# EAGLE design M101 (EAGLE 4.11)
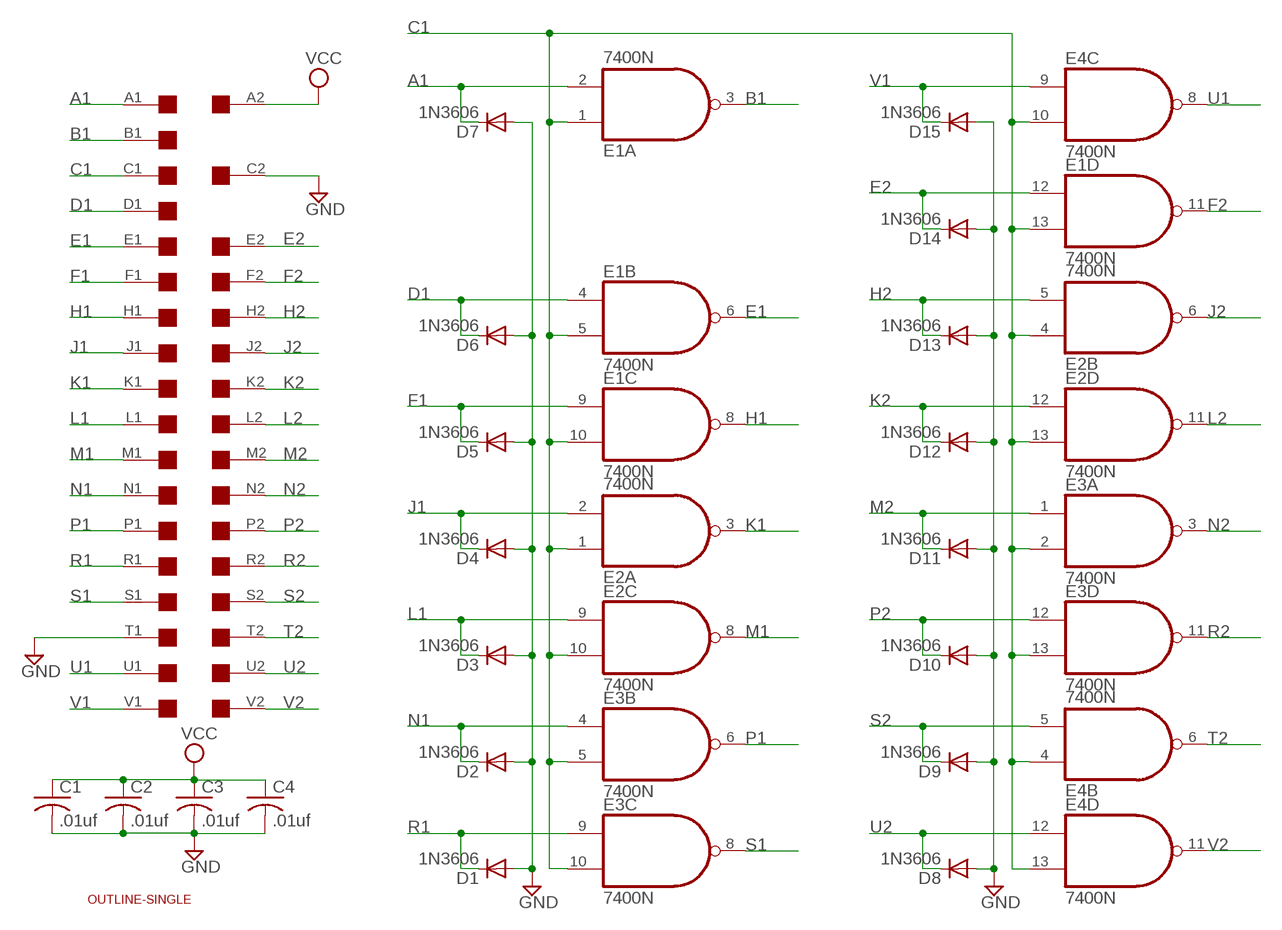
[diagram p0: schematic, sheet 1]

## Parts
C1  .01uf  C-US050-025X075  [C050-025X075]
C2  .01uf  C-US050-025X075  [C050-025X075]
C3  .01uf  C-US050-025X075  [C050-025X075]
C4  .01uf  C-US050-025X075  [C050-025X075]
D1  1N3606  1N4148  [DO35-10]
D2  1N3606  1N4148  [DO35-10]
D3  1N3606  1N4148  [DO35-10]
D4  1N3606  1N4148  [DO35-10]
D5  1N3606  1N4148  [DO35-10]
D6  1N3606  1N4148  [DO35-10]
D7  1N3606  1N4148  [DO35-10]
D8  1N3606  1N4148  [DO35-10]
D9  1N3606  1N4148  [DO35-10]
D10  1N3606  1N4148  [DO35-10]
D11  1N3606  1N4148  [DO35-10]
D12  1N3606  1N4148  [DO35-10]
D13  1N3606  1N4148  [DO35-10]
D14  1N3606  1N4148  [DO35-10]
D15  1N3606  1N4148  [DO35-10]
E1  7400N  [DIL14]
E2  7400N  [DIL14]
E3  7400N  [DIL14]
E4  7400N  [DIL14]
U$1  SINGLE  [EDGE-CON2]
U$4  OUTLINE-SINGLE  [SINGLE]

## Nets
A1: D7.C E1.2(A:I1) U$1.A1
B1: E1.3(A:O) U$1.B1
C1: E1.1(A:I0) E1.5(B:I1) E1.10(C:I1) E1.13(D:I1) E2.1(A:I0) E2.4(B:I0) E2.10(C:I1) E2.13(D:I1) E3.2(A:I1) E3.5(B:I1) E3.10(C:I1) E3.13(D:I1) E4.4(B:I0) E4.10(C:I1) E4.13(D:I1) U$1.C1
D1: D6.C E1.4(B:I0) U$1.D1
E1: E1.6(B:O) U$1.E1
E2: D14.C E1.12(D:I0) U$1.E2
F1: D5.C E1.9(C:I0) U$1.F1
F2: E1.11(D:O) U$1.F2
GND: C1.2 C2.2 C3.2 C4.2 D1.A D2.A D3.A D4.A D5.A D6.A D7.A D8.A D9.A D10.A D11.A D12.A D13.A D14.A D15.A U$1.C2 U$1.T1
H1: E1.8(C:O) U$1.H1
H2: D13.C E2.5(B:I1) U$1.H2
J1: D4.C E2.2(A:I1) U$1.J1
J2: E2.6(B:O) U$1.J2
K1: E2.3(A:O) U$1.K1
K2: D12.C E2.12(D:I0) U$1.K2
L1: D3.C E2.9(C:I0) U$1.L1
L2: E2.11(D:O) U$1.L2
M1: E2.8(C:O) U$1.M1
M2: D11.C E3.1(A:I0) U$1.M2
N1: D2.C E3.4(B:I0) U$1.N1
N2: E3.3(A:O) U$1.N2
P1: E3.6(B:O) U$1.P1
P2: D10.C E3.12(D:I0) U$1.P2
R1: D1.C E3.9(C:I0) U$1.R1
R2: E3.11(D:O) U$1.R2
S1: E3.8(C:O) U$1.S1
S2: D9.C E4.5(B:I1) U$1.S2
T2: E4.6(B:O) U$1.T2
U1: E4.8(C:O) U$1.U1
U2: D8.C E4.12(D:I0) U$1.U2
V1: D15.C E4.9(C:I0) U$1.V1
V2: E4.11(D:O) U$1.V2
VCC: C1.1 C2.1 C3.1 C4.1 U$1.A2
Unconnected: E4.1(A:I0) E4.2(A:I1) E4.3(A:O) U$1.B2 U$1.D2

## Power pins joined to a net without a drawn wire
GND: E1.7(P:GND) E2.7(P:GND) E3.7(P:GND) E4.7(P:GND)
VCC: E1.14(P:VCC) E2.14(P:VCC) E3.14(P:VCC) E4.14(P:VCC)

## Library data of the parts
C1-C4 = rcl:C-US: CAPACITOR, American symbol
D1-D15 = diode:1N4148: DIODE
E1-E4 = 74xx-us:74*00: Quad 2-input NAND gate
U$1 = dec-con:SINGLE: Single-Height DEC board
U$4 = dec-con:OUTLINE-*: Board outlines for DEC boards.

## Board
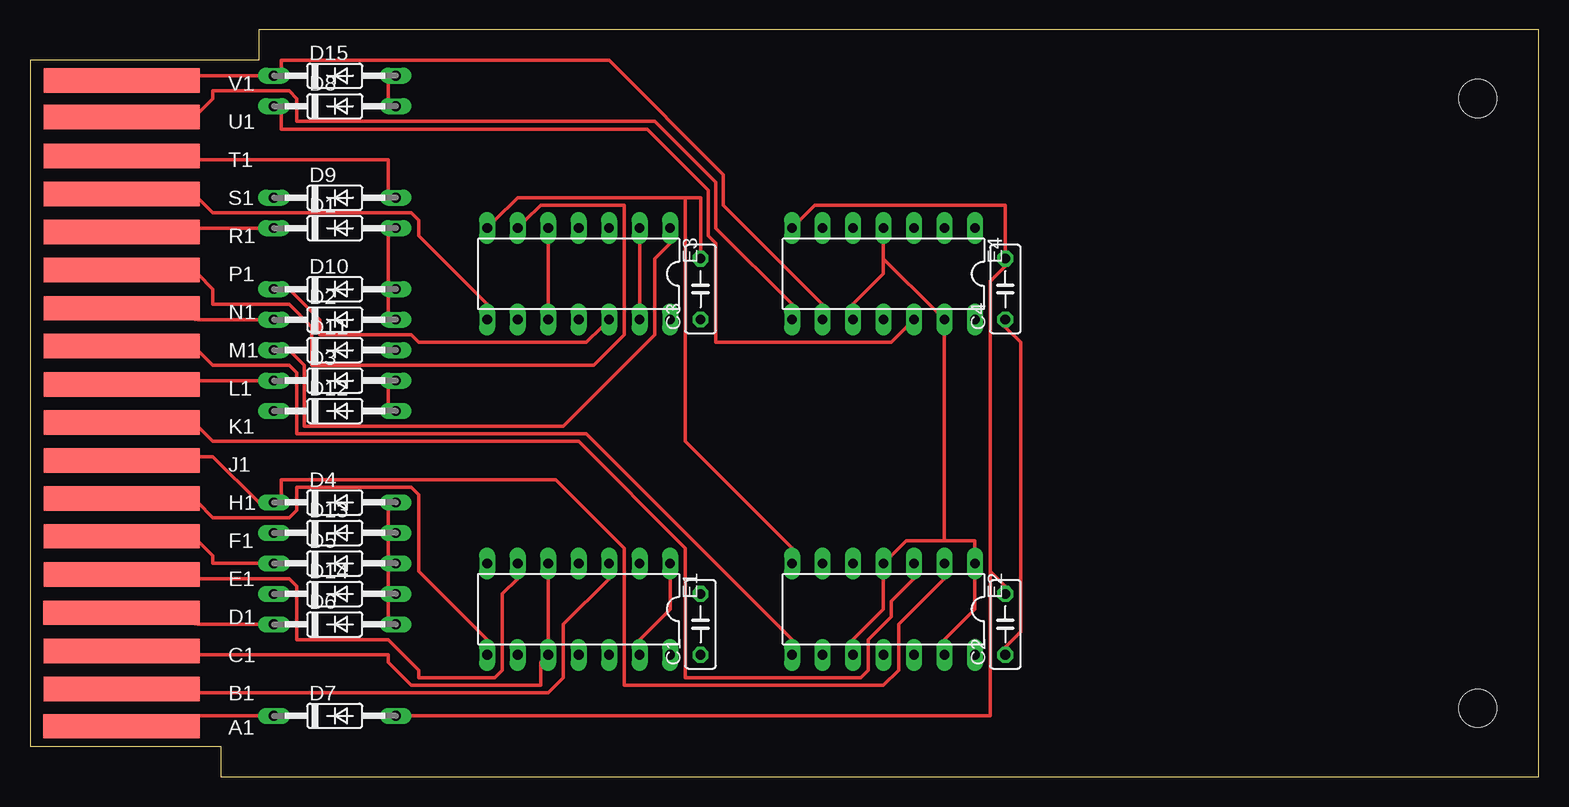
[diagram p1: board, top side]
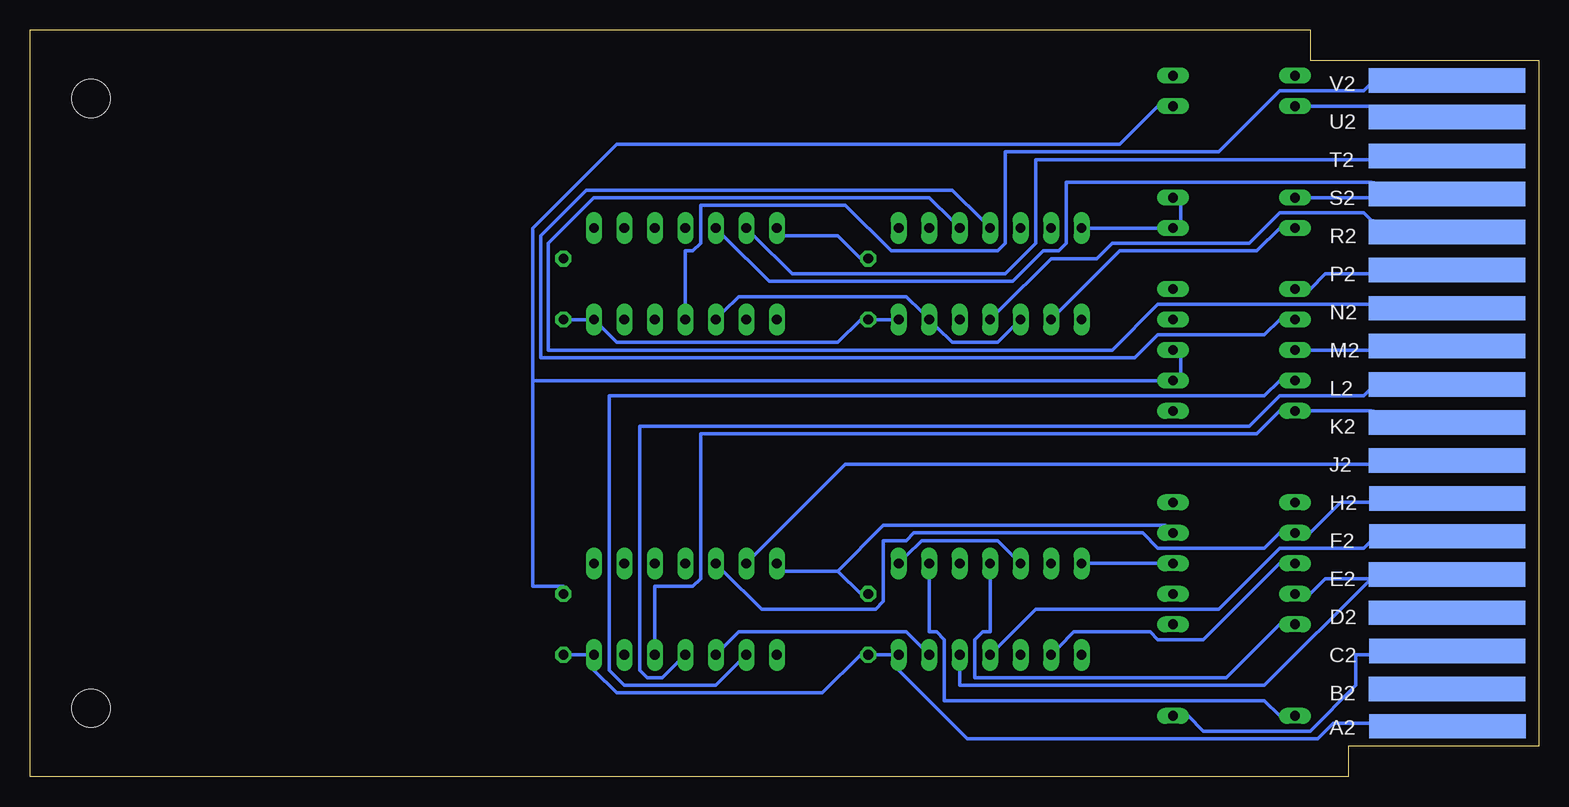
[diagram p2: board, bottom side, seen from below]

Size 125.73 x 62.23 mm. Coordinates in mm from the lower left corner, seen from the top.
Copper layers (1*16): Top 0.035mm / dielectric 1.5mm / Bottom 0.035mm
Design rules "10mils": minimum track width 12mil, minimum drill 28mil, track to track 10mil, track to pad 10mil, pad to pad 10mil, via to via 10mil, smd to smd 10mil, copper to edge 40mil, drill to drill 10mil, minimum pad ring 10mil, minimum via ring 8mil, stop-mask expansion 0mil, vias tented up to drill 0mil, thermal gap 10mil

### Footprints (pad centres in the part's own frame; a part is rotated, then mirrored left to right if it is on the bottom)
C050-025X075 = drill 0.813 octagon: 1 -2.54,0; 2 2.54,0
DO35-10 = drill 0.813 long: A 5.08,0; C -5.08,0
DIL14 = drill 0.813 long: 1 -7.62,-3.81; 2 -5.08,-3.81; 3 -2.54,-3.81; 4 0,-3.81; 5 2.54,-3.81; 6 5.08,-3.81; 7 7.62,-3.81; 8 7.62,3.81; 9 5.08,3.81; 10 2.54,3.81; 11 0,3.81; 12 -2.54,3.81; 13 -5.08,3.81; 14 -7.62,3.81
EDGE-CON2 = smd 13.017 x 2.032: A1 7.633,4.207; B1 7.639,7.327; C1 7.636,10.489; D1 7.633,13.665; E1 7.642,16.84; F1 7.642,20.041; H1 7.642,23.19; J1 7.642,26.34; K1 7.642,29.515; L1 7.642,32.69; M1 7.642,35.89; N1 7.642,39.04; P1 7.642,42.24; R1 7.642,45.39; S1 7.642,48.565; T1 7.642,51.74; U1 7.642,54.966; V1 7.642,58.026 | smd 13.017 x 2.032 bottom: A2 7.614,4.207; B2 7.642,7.328; C2 7.617,10.49; D2 7.642,13.665; E2 7.642,16.84; F2 7.617,20.041; H2 7.617,23.19; J2 7.642,26.34; K2 7.642,29.515; L2 7.642,32.69; M2 7.642,35.89; N2 7.642,39.04; P2 7.642,42.24; R2 7.642,45.39; S2 7.642,48.565; T2 7.642,51.74; U2 7.642,54.966; V2 7.642,58.026
SINGLE = hole 3.175: 120.65,56.515; 120.65,5.715

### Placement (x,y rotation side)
C1  55.88,12.7 90 top
C2  81.28,12.7 90 top
C3  55.88,40.64 90 top
C4  81.28,40.64 90 top
D1  25.4,45.72 0 top
D2  25.4,38.1 0 top
D3  25.4,33.02 0 top
D4  25.4,22.86 0 top
D5  25.4,17.78 0 top
D6  25.4,12.7 0 top
D7  25.4,5.08 0 top
D8  25.4,55.88 0 top
D9  25.4,48.26 0 top
D10  25.4,40.64 0 top
D11  25.4,35.56 0 top
D12  25.4,30.48 0 top
D13  25.4,20.32 0 top
D14  25.4,15.24 0 top
D15  25.4,58.42 0 top
E1  45.72,13.97 180 top
E2  71.12,13.97 180 top
E3  45.72,41.91 180 top
E4  71.12,41.91 180 top
U$1  0,0 0 top
U$4  0,0 0 top

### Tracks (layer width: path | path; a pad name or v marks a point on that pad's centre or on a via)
A1
  Top 0.305: D7.C 19.05,5.08 13.97,5.08 U$1.A1
  Bottom 0.305: E1.2 50.8,16.51 50.8,12.06 50.17,12.06 49.53,11.43 49.53,6.35 22.86,6.35 21.59,5.08 D7.C
B1
  Top 0.305: 13.97,6.99 43.18,6.99 44.45,8.26 44.45,12.7 48.26,16.51 E1.3 | 13.97,6.99 13.97,7.62 | U$1.B1 13.97,6.99
C1
  Top 0.305: E1.5 43.18,16.51 43.18,11.43 E1.10 42.55,9.53 42.55,7.62 31.75,7.62 29.85,9.53 29.85,10.16 13.97,10.16 U$1.C1 | E1.13 50.8,11.43 53.34,13.97 53.34,16.51 E1.1 | E3.10 43.18,39.37 43.18,44.45 E3.5 | E3.13 50.8,39.37 50.8,44.45 E3.2 | 71.12,43.18 71.12,44.45 E4.4 | 71.12,43.18 71.12,41.91 68.58,39.37 E4.10 | 71.12,43.18 75.57,38.73 E4.13 76.2,36.83 76.2,19.68 | E2.10 68.58,11.43 71.12,13.97 71.12,16.51 E2.4 71.76,18.41 73.03,19.68 76.2,19.68 | E2.13 76.2,11.43 78.74,13.97 78.74,16.51 E2.1 78.74,19.05 78.74,19.68 76.2,19.68
  Bottom 0.305: E1.5 43.82,18.41 45.09,19.68 51.44,19.68 52.71,18.41 E1.1 | E3.10 43.82,37.47 45.09,36.2 48.9,36.2 50.17,37.47 E3.13 51.44,38.73 52.71,40.01 66.68,40.01 67.95,38.73 E4.10 | E1.13 51.44,10.79 52.71,12.06 66.68,12.06 67.95,10.79 E2.10
D1
  Top 0.305: 13.97,12.7 19.05,12.7 D6.C | 13.97,12.7 13.97,13.34 | U$1.D1 13.97,12.7
  Bottom 0.305: E1.4 45.72,16.51 45.72,12.06 46.36,12.06 46.99,11.43 46.99,8.26 26.04,8.26 21.59,12.7 D6.C
E1
  Top 0.305: E1.6 40.64,16.51 39.37,15.24 39.37,8.89 38.74,8.26 32.39,8.26 32.39,8.89 29.85,11.43 22.23,11.43 22.23,15.88 21.59,16.51 13.97,16.51 U$1.E1
E2
  Bottom 0.305: 13.97,16.51 17.78,16.51 19.05,15.24 D14.C | 13.97,16.51 22.86,7.62 48.26,7.62 48.26,8.89 E1.12 | U$1.E2 13.97,16.51
F1
  Top 0.305: D5.C 19.05,17.78 15.24,17.78 15.24,18.41 13.97,19.68 U$1.F1
  Bottom 0.305: E1.9 40.01,10.79 38.74,12.06 32.39,12.06 31.75,11.43 27.94,11.43 21.59,17.78 D5.C
F2
  Bottom 0.305: E1.11 45.09,10.79 41.91,13.97 26.67,13.97 21.59,19.05 14.61,19.05 13.97,19.68 U$1.F2
GND
  Top 0.305: D6.A 29.85,13.34 29.85,14.61 D14.A 29.85,15.88 29.85,17.14 D5.A 29.85,18.41 29.85,19.68 D13.A 29.85,20.95 29.85,22.23 D4.A | D2.A 29.85,38.73 29.85,40.01 D10.A 29.85,41.27 29.85,45.09 D1.A | D12.A 29.85,31.11 29.85,32.38 D3.A | D8.A 29.85,56.52 29.85,57.78 D15.A | 80.01,17.14 81.28,15.88 C2.2 | 80.01,17.14 80.01,41.27 81.28,42.55 C4.2 81.28,43.81 81.28,47.62 65.41,47.62 64.14,46.35 E4.7 | 54.61,48.26 55.88,48.26 55.88,43.81 C3.2 | 54.61,48.26 40.64,48.26 38.74,46.35 E3.7 | D9.A 29.85,48.9 29.85,51.44 13.97,51.44 U$1.T1 | 54.61,48.26 54.61,27.94 63.5,19.05 E2.7 | 80.01,17.14 80.01,5.08 31.75,5.08 D7.A
  Bottom 0.305: D7.A 29.21,5.08 27.94,3.81 19.05,3.81 15.24,7.62 15.24,10.16 13.97,10.16 U$1.C2 | 58.42,17.14 56.52,15.24 C1.2 | 58.42,17.14 62.87,17.14 E2.7 | E1.7 37.47,17.78 31.75,17.78 D5.A | 58.42,17.14 54.61,20.95 31.12,20.95 D13.A | D9.A 29.85,47.62 29.85,46.35 D1.A 31.75,45.72 37.47,45.72 E3.7 | C3.2 56.52,43.18 58.42,45.09 62.87,45.09 E4.7 | D11.A 29.85,34.92 29.85,33.66 D3.A 31.75,33.02 83.82,33.02 | 83.82,33.02 83.82,15.88 81.28,15.88 C2.2 | 83.82,33.02 83.82,45.72 76.84,52.7 34.93,52.7 31.75,55.88 D8.A
H1
  Top 0.305: E1.8 38.1,11.43 32.39,17.14 32.39,23.5 31.75,24.13 22.23,24.13 22.23,22.23 21.59,21.59 15.24,21.59 13.97,22.86 U$1.H1
H2
  Bottom 0.305: E2.5 67.95,17.14 64.77,13.97 55.25,13.97 54.61,14.61 54.61,19.68 52.71,19.68 52.07,20.32 33.02,20.32 31.75,19.05 22.86,19.05 21.59,20.32 D13.C 19.05,20.32 16.51,22.86 13.97,22.86 U$1.H2
J1
  Top 0.305: E2.2 76.2,16.51 72.39,12.7 72.39,8.89 71.12,7.62 49.53,7.62 49.53,19.05 43.82,24.77 20.96,24.77 20.96,23.5 D4.C 19.05,22.86 15.24,26.67 13.97,26.67 U$1.J1
J2
  Bottom 0.305: E2.6 65.41,18.41 57.79,26.04 13.97,26.04 U$1.J2
K1
  Top 0.305: E2.3 73.66,16.51 71.76,14.61 71.76,13.34 69.85,11.43 69.85,8.89 69.22,8.26 54.61,8.26 54.61,19.05 45.72,27.94 15.24,27.94 13.97,29.21 U$1.K1
K2
  Bottom 0.305: E2.12 73.66,11.43 73.66,15.88 70.49,15.88 69.85,16.51 69.85,28.57 23.5,28.57 21.59,30.48 D12.C 19.05,30.48 13.97,30.48 U$1.K2
L1
  Top 0.305: D3.C 19.05,33.02 13.97,33.02 U$1.L1
  Bottom 0.305: E2.9 66.68,9.53 68.58,7.62 76.2,7.62 77.47,8.89 77.47,31.75 22.86,31.75 21.59,33.02 D3.C
L2
  Bottom 0.305: E2.11 71.76,9.53 73.03,8.26 74.3,8.26 74.93,8.89 74.93,29.21 24.13,29.21 21.59,31.75 14.61,31.75 13.97,32.38 U$1.L2
M1
  Top 0.305: E2.8 63.5,11.43 46.36,28.57 22.23,28.57 22.23,33.66 21.59,34.29 15.24,34.29 13.97,35.56 U$1.M1
M2
  Top 0.305: E3.1 53.34,44.45 52.07,43.18 52.07,36.83 44.45,29.21 22.86,29.21 22.86,34.29 21.59,35.56 D11.C
  Bottom 0.305: D11.C 19.05,35.56 13.97,35.56 U$1.M2
N1
  Top 0.305: 13.97,38.1 19.05,38.1 D2.C | 13.97,38.1 13.97,38.73 | U$1.N1 13.97,38.1
  Bottom 0.305: E3.4 46.36,46.35 48.9,48.9 79.38,48.9 83.19,45.09 83.19,34.92 33.66,34.92 31.75,36.83 22.86,36.83 21.59,38.1 D2.C
N2
  Bottom 0.305: E3.3 48.9,46.35 50.8,48.26 78.74,48.26 82.55,44.45 82.55,35.56 35.56,35.56 31.75,39.37 13.97,39.37 U$1.N2
P1
  Top 0.305: E3.6 41.28,46.35 42.55,47.62 49.53,47.62 49.53,36.83 46.99,34.29 23.5,34.29 23.5,37.47 21.59,39.37 15.24,39.37 15.24,40.64 13.97,41.91 U$1.P1
P2
  Top 0.305: E3.12 47.63,37.47 46.36,36.2 32.39,36.2 31.75,36.83 24.13,36.83 24.13,38.1 21.59,40.64 D10.C
  Bottom 0.305: D10.C 19.05,40.64 17.78,41.91 13.97,41.91 U$1.P2
R1
  Top 0.305: D1.C 19.05,45.72 13.97,45.72 U$1.R1
  Bottom 0.305: E3.9 40.01,38.73 34.93,43.81 23.5,43.81 21.59,45.72 D1.C
R2
  Bottom 0.305: E3.11 45.09,38.73 40.64,43.18 36.83,43.18 35.56,44.45 24.13,44.45 21.59,46.99 14.61,46.99 13.97,46.35 U$1.R2
S1
  Top 0.305: E3.8 38.1,39.37 32.39,45.09 32.39,46.35 31.75,46.99 15.24,46.99 13.97,48.26 U$1.S1
S2
  Bottom 0.305: D9.C 19.05,48.26 13.97,48.26 U$1.S2 13.97,49.53 39.37,49.53 39.37,44.45 40.01,43.81 41.28,43.81 43.82,41.27 64.14,41.27 67.95,45.09 E4.5
T2
  Bottom 0.305: E4.6 65.41,45.09 62.23,41.91 44.45,41.91 41.91,44.45 41.91,51.44 13.97,51.44 U$1.T2
U1
  Top 0.305: E4.8 63.5,39.37 57.15,45.72 57.15,49.53 52.07,54.61 22.23,54.61 22.23,56.52 21.59,57.15 15.24,57.15 15.24,56.52 13.97,55.24 U$1.U1
U2
  Top 0.305: E4.12 73.03,37.47 71.76,36.2 57.15,36.2 57.15,44.45 56.52,45.09 56.52,48.9 51.44,53.98 20.96,53.98 20.96,55.24 D8.C
  Bottom 0.305: D8.C 19.05,55.88 13.97,55.88 U$1.U2
V1
  Top 0.305: E4.9 66.04,39.37 57.79,47.62 57.79,50.16 48.26,59.69 20.96,59.69 20.96,59.05 D15.C 19.05,58.42 13.97,58.42 U$1.V1
V2
  Bottom 0.305: E4.11 71.12,39.37 71.12,43.81 70.49,43.81 69.85,44.45 69.85,47.62 57.79,47.62 53.98,43.81 45.09,43.81 44.45,44.45 44.45,52.07 26.67,52.07 21.59,57.15 14.61,57.15 13.97,57.78 U$1.V2
VCC
  Top 0.305: C4.1 81.28,37.47 82.55,36.2 82.55,12.06 81.28,10.79 C2.1
  Bottom 0.305: E3.14 53.98,38.1 55.25,38.1 C3.1 56.52,38.1 58.42,36.2 76.84,36.2 78.11,37.47 E4.14 79.38,38.1 80.65,38.1 C4.1 | C2.1 80.65,10.16 79.38,10.16 E2.14 78.74,8.89 76.84,6.99 59.69,6.99 56.52,10.16 C1.1 55.25,10.16 53.98,10.16 E1.14 53.34,8.89 47.63,3.17 18.42,3.17 17.15,4.45 14.61,4.45 13.97,4.45 U$1.A2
